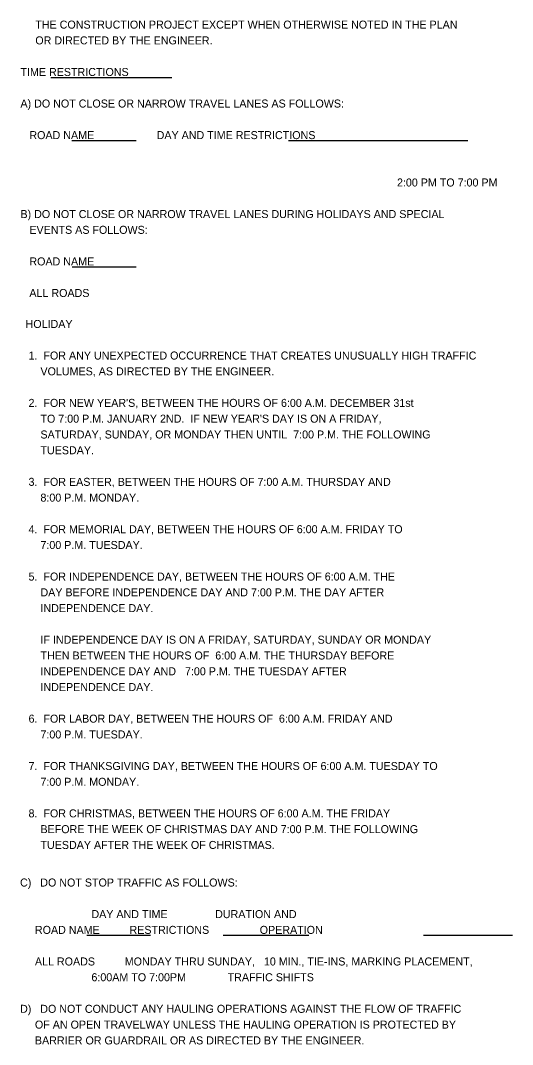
# Model space of a CAD drawing. Extents: x 762655 to 770567, y 650864 to 655190.
# Drawn here: x 763054 to 763423, y 650864 to 651632 of the extents above; entities that cross this region are included whole.
import ezdxf

# ---------------------------------------------------------------- set-up
doc = ezdxf.new("R2010")
doc.units = 0
doc.layers.add('Default', color=7, linetype='Continuous')

msp = doc.modelspace()

# ---------------------------------------------------------------- linework, layer by layer
at = {"layer": 'Default'}
for p, q in [((763076.42, 651589.18), (763167.12, 651589.18)), ((763092.18, 651541.85), (763140.41, 651541.85)), ((763254.64, 651541.85), (763389.06, 651541.85)), ((763092.41, 651447.21), (763140.29, 651447.21)), ((763103.29, 650946.12), (763151.03, 650946.12)), ((763205.64, 650946.12), (763269.82, 650946.12)), ((763355.74, 650946.12), (763422.51, 650946.12))]:
    msp.add_line(p, q, dxfattribs=at)

# ---------------------------------------------------------------- texts
for s, p in [('            THE CONSTRUCTION PROJECT EXCEPT WHEN OTHERWISE NOTED IN THE PLAN', (763038.05, 651625.75)), ('            OR DIRECTED BY THE ENGINEER.', (763038.05, 651613.92)), ('       TIME RESTRICTIONS ', (763038.05, 651590.25)), ('       A) DO NOT CLOSE OR NARROW TRAVEL LANES AS FOLLOWS:', (763038.05, 651566.59)), ('          ROAD NAME                     DAY AND TIME RESTRICTIONS', (763038.05, 651542.92)), ('        2:00 PM TO 7:00 PM', (763318.06, 651507.42)), ('       B) DO NOT CLOSE OR NARROW TRAVEL LANES DURING HOLIDAYS AND SPECIAL', (763038.05, 651483.75)), ('          EVENTS AS FOLLOWS:', (763038.05, 651471.92)), ('          ROAD NAME ', (763038.05, 651448.25)), ('          ALL ROADS ', (763038.05, 651424.59)), ('           HOLIDAY', (763032.97, 651401.37)), ('            1.  FOR ANY UNEXPECTED OCCURRENCE THAT CREATES UNUSUALLY HIGH TRAFFIC ', (763032.97, 651377.7)), ('                VOLUMES, AS DIRECTED BY THE ENGINEER.', (763032.97, 651365.87)), ("            2.  FOR NEW YEAR'S, BETWEEN THE HOURS OF 6:00 A.M. DECEMBER 31st", (763032.97, 651342.2)), ("                TO 7:00 P.M. JANUARY 2ND.  IF NEW YEAR'S DAY IS ON A FRIDAY,", (763032.97, 651330.37)), ('                SATURDAY, SUNDAY, OR MONDAY THEN UNTIL  7:00 P.M. THE FOLLOWING ', (763032.97, 651318.53)), ('                TUESDAY.  ', (763032.97, 651306.7)), ('            3.  FOR EASTER, BETWEEN THE HOURS OF 7:00 A.M. THURSDAY AND', (763032.97, 651283.03)), ('                8:00 P.M. MONDAY.', (763032.97, 651271.2)), ('            4.  FOR MEMORIAL DAY, BETWEEN THE HOURS OF 6:00 A.M. FRIDAY TO', (763032.97, 651247.53)), ('                7:00 P.M. TUESDAY.', (763032.97, 651235.7)), ('            5.  FOR INDEPENDENCE DAY, BETWEEN THE HOURS OF 6:00 A.M. THE', (763032.97, 651212.03)), ('                DAY BEFORE INDEPENDENCE DAY AND 7:00 P.M. THE DAY AFTER', (763032.97, 651200.2)), ('                INDEPENDENCE DAY.', (763032.97, 651188.37)), ('                IF INDEPENDENCE DAY IS ON A FRIDAY, SATURDAY, SUNDAY OR MONDAY  ', (763032.97, 651164.7)), ('                THEN BETWEEN THE HOURS OF  6:00 A.M. THE THURSDAY BEFORE ', (763032.97, 651152.87)), ('                INDEPENDENCE DAY AND   7:00 P.M. THE TUESDAY AFTER', (763032.97, 651141.03)), ('                INDEPENDENCE DAY.   ', (763032.97, 651129.2)), ('            6.  FOR LABOR DAY, BETWEEN THE HOURS OF  6:00 A.M. FRIDAY AND', (763032.97, 651105.53)), ('                7:00 P.M. TUESDAY.', (763032.97, 651093.7)), ('            7.  FOR THANKSGIVING DAY, BETWEEN THE HOURS OF 6:00 A.M. TUESDAY TO', (763032.97, 651070.03)), ('                7:00 P.M. MONDAY.', (763032.97, 651058.2)), ('            8.  FOR CHRISTMAS, BETWEEN THE HOURS OF 6:00 A.M. THE FRIDAY', (763032.97, 651034.53)), ('                BEFORE THE WEEK OF CHRISTMAS DAY AND 7:00 P.M. THE FOLLOWING', (763032.97, 651022.7)), ('                TUESDAY AFTER THE WEEK OF CHRISTMAS.', (763032.97, 651010.87)), ('       C)   DO NOT STOP TRAFFIC AS FOLLOWS:  ', (763037.75, 650982.7)), ('                               DAY AND TIME                DURATION AND', (763037.75, 650959.03)), ('            ROAD NAME          RESTRICTIONS                 OPERATION', (763037.75, 650947.2)), ('            ALL ROADS          MONDAY THRU SUNDAY,   10 MIN., TIE-INS, MARKING PLACEMENT,', (763037.75, 650923.53)), ('                               6:00AM TO 7:00PM              TRAFFIC SHIFTS', (763037.75, 650911.7)), ('       D)   DO NOT CONDUCT ANY HAULING OPERATIONS AGAINST THE FLOW OF TRAFFIC', (763037.75, 650888.03)), ('            OF AN OPEN TRAVELWAY UNLESS THE HAULING OPERATION IS PROTECTED BY', (763037.75, 650876.2)), ('            BARRIER OR GUARDRAIL OR AS DIRECTED BY THE ENGINEER.', (763037.75, 650864.36))]:
    msp.add_text(s, height=6, dxfattribs=at).set_placement(p)

doc.saveas('drawing.dxf')
